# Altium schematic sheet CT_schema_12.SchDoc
size 382 x 278 mm
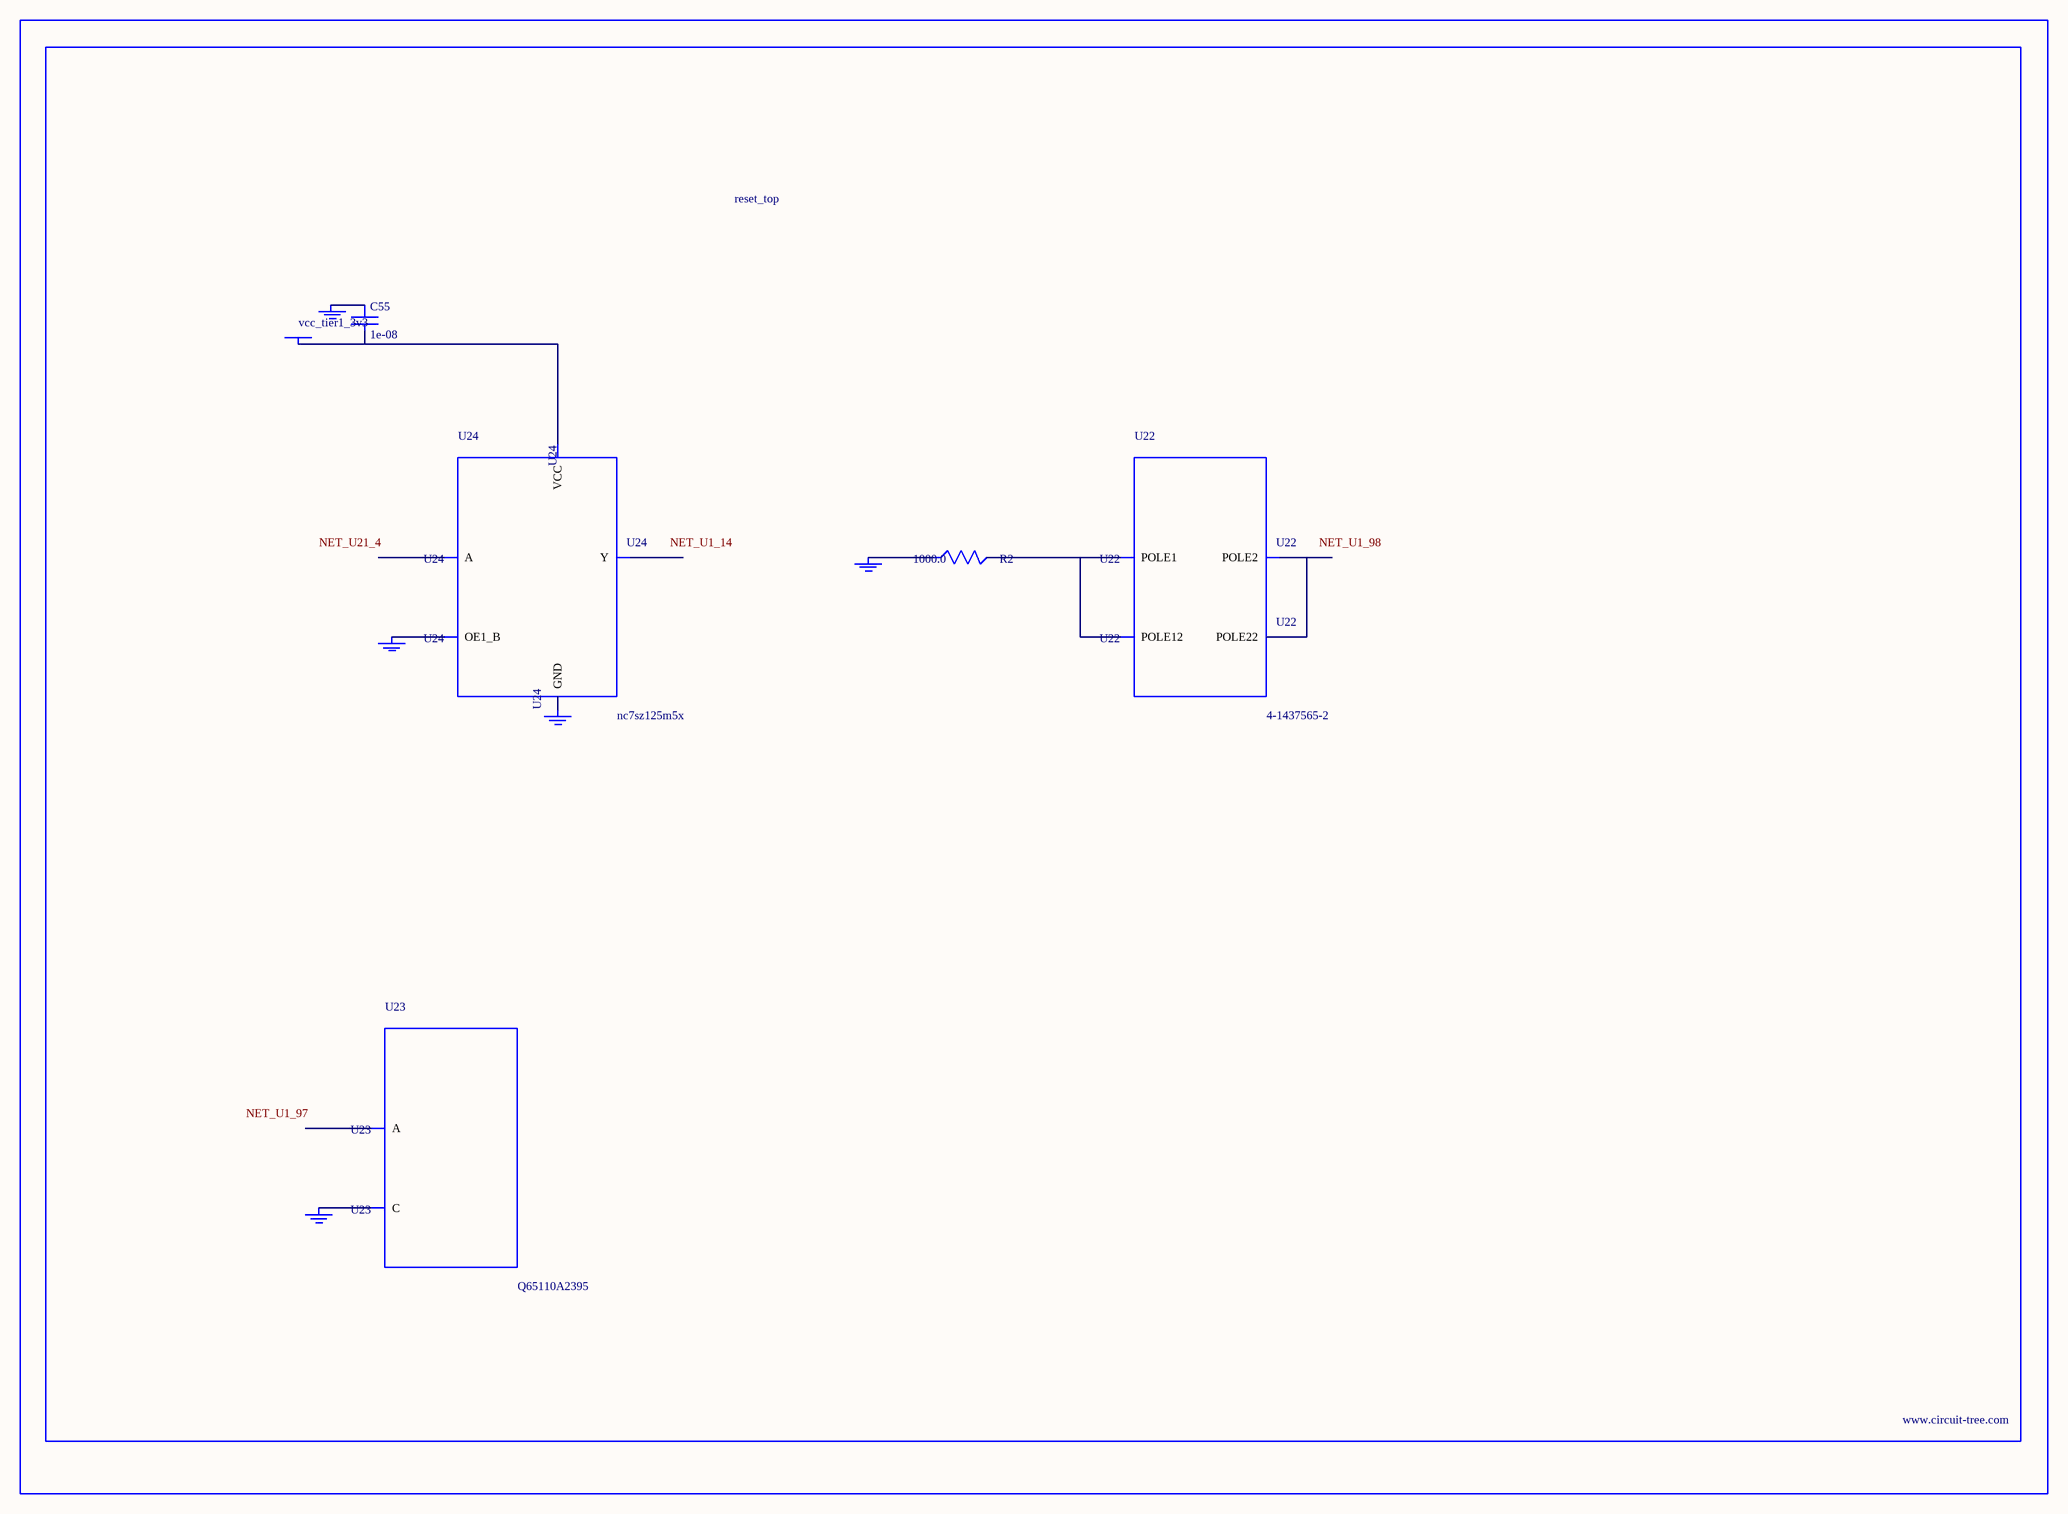
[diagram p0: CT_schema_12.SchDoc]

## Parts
BORDER11  (no value)
C55  1e-08  [C0402]
GND_INSTANCE_11_0  (no value)
GND_INSTANCE_11_1  (no value)
GND_INSTANCE_11_2  (no value)
GND_INSTANCE_11_3  (no value)
GND_INSTANCE_11_4  (no value)
POWER_INSTANCE_11_0  vcc_tier1_3v3
R2  1000.0  [R0603]
U22  4-1437565-2  [SW_4-1437565-2]
U23  Q65110A2395  [LGM67K-G1J2-24-Z]
U24  nc7sz125m5x  [NC7SZ125M5X]

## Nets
NetC55_1: C55.1 GND_INSTANCE_11_2.0(GND)
NetC55_2: C55.2 POWER_INSTANCE_11_0.0(PWR) U24.5(VCC)
NetGND_INSTANCE_11_0_0: GND_INSTANCE_11_0.0(GND) R2.1
NetGND_INSTANCE_11_1_0: GND_INSTANCE_11_1.0(GND) U23.C
NetGND_INSTANCE_11_3_0: GND_INSTANCE_11_3.0(GND) U24.1(OE1_B)
NetGND_INSTANCE_11_4_0: GND_INSTANCE_11_4.0(GND) U24.3(GND)
NetR2_2: R2.2 U22.1(POLE1) U22.2(POLE12)
NetU22_3: U22.3(POLE2) U22.4(POLE22)

Not connected (* = marked no-connect by the designer): U23 A; U24 2(A) 4(Y)

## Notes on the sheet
- Labels drawn without touching a wire or pin: NET_U1_14, NET_U1_97, NET_U1_98, NET_U21_4

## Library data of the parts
BORDER11 = BORDER_PAGE11
C55 = C0402C103K3RAC
GND_INSTANCE_11_0-GND_INSTANCE_11_4 = GND
POWER_INSTANCE_11_0 = PWR
R2 = RC0603JR-071KL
